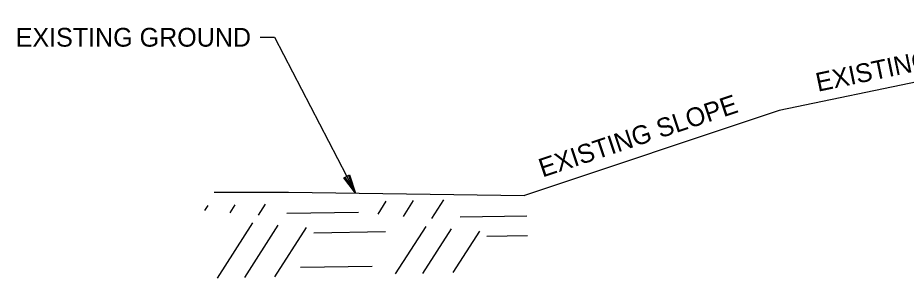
# Model space of a CAD drawing. Extents: x 1398183 to 1398373, y 1967240 to 1968889.
# Drawn here: x 1398196.57 to 1398224.54, y 1967304.84 to 1967313.04 of the extents above; entities that cross this region are included whole.
import ezdxf

# ---------------------------------------------------------------- set-up
doc = ezdxf.new("R2010")
doc.units = 0
for name, color, linetype in [('10', 7, 'Continuous'), ('19', 7, 'Continuous'), ('42', 7, 'Continuous'), ('9', 7, 'Continuous')]:
    doc.layers.add(name, color=color, linetype=linetype)

msp = doc.modelspace()

# ---------------------------------------------------------------- linework, layer by layer
at = {"layer": '19'}
for p, q in [((1398206.829, 1967308), (1398207.015, 1967308.095)), ((1398206.975, 1967308.071), (1398207.138, 1967307.665)), ((1398207.015, 1967308.095), (1398207.199, 1967307.516)), ((1398207.199, 1967307.516), (1398206.829, 1967308)), ((1398207.116, 1967307.652), (1398206.879, 1967308.02))]:
    msp.add_line(p, q, dxfattribs=at)
msp.add_lwpolyline([(1398204.199, 1967312.422), (1398204.645, 1967312.422), (1398207.199, 1967307.516)], dxfattribs=at)
at = {"layer": '42'}
for p, q in [((1398234.544, 1967313.036), (1398220.544, 1967310.119)), ((1398220.544, 1967310.119), (1398212.517, 1967307.443))]:
    msp.add_line(p, q, dxfattribs=at)
msp.add_lwpolyline([(1398202.748, 1967307.544), (1398205.086, 1967307.544), (1398212.517, 1967307.443)], dxfattribs=at)
at = {"layer": '9'}
for p, q in [((1398207.91, 1967306.859), (1398208.167, 1967307.26)), ((1398208.71, 1967306.785), (1398209.027, 1967307.28)), ((1398209.602, 1967306.713), (1398209.979, 1967307.303)), ((1398202.456, 1967306.97), (1398202.556, 1967307.126)), ((1398203.255, 1967306.896), (1398203.415, 1967307.147)), ((1398204.147, 1967306.825), (1398204.367, 1967307.169)), ((1398205.035, 1967306.883), (1398207.297, 1967306.918)), ((1398210.49, 1967306.772), (1398212.596, 1967306.804)), ((1398202.852, 1967304.838), (1398203.967, 1967306.579)), ((1398203.711, 1967304.859), (1398204.766, 1967306.505)), ((1398204.664, 1967304.881), (1398205.658, 1967306.434)), ((1398208.464, 1967304.972), (1398209.422, 1967306.468)), ((1398209.323, 1967304.992), (1398210.221, 1967306.394)), ((1398205.884, 1967306.272), (1398208.146, 1967306.308)), ((1398210.275, 1967305.015), (1398211.113, 1967306.323)), ((1398211.339, 1967306.161), (1398212.611, 1967306.181)), ((1398205.465, 1967305.186), (1398207.727, 1967305.222))]:
    msp.add_line(p, q, dxfattribs=at)

# ---------------------------------------------------------------- texts
at = {"layer": '10'}
msp.add_text('EXISTING GROUND', height=0.59001, dxfattribs=at).set_placement((1398196.501, 1967312.127))
for rotation, p in [(11.7678, (1398221.76, 1967310.705)), (18.4349, (1398213.09, 1967308.006))]:
    msp.add_text('EXISTING SLOPE', height=0.59001, rotation=rotation, dxfattribs=at).set_placement(p)

doc.saveas('drawing.dxf')
